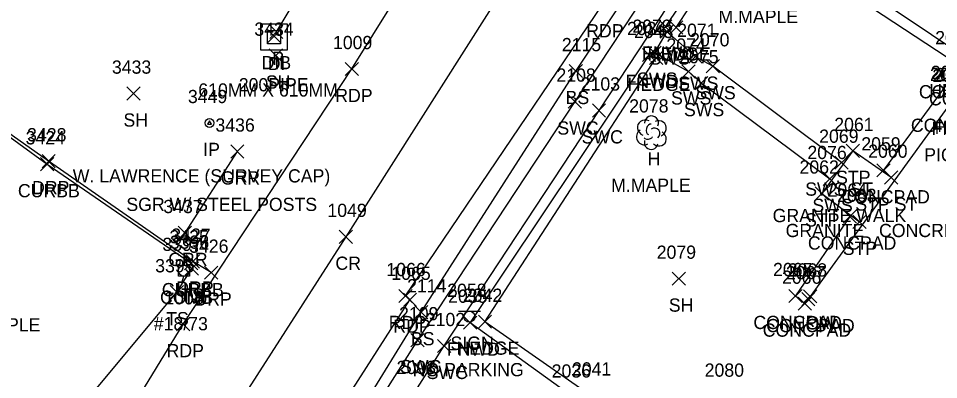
# Model space of a CAD drawing. Extents: x 1634209 to 1639641, y 608564 to 612258.
# Drawn here: x 1639014.2 to 1639153.3, y 611150.8 to 611205.4 of the extents above; entities that cross this region are included whole.
import ezdxf

# ---------------------------------------------------------------- set-up
doc = ezdxf.new("R2010")
doc.units = 0
for name, color, linetype in [('D_A', 7, 'Continuous'), ('D_C', 7, 'Continuous'), ('D_TIC', 7, 'Continuous'), ('DCP', 7, 'Continuous'), ('DS', 7, 'Continuous'), ('L_A', 7, 'Continuous'), ('L_C', 7, 'Continuous'), ('L_I', 7, 'Continuous'), ('L_TIC', 7, 'Continuous'), ('LAHR', 7, 'Continuous'), ('LBC', 7, 'Continuous'), ('LBF', 7, 'Continuous'), ('LELB', 7, 'Continuous'), ('LFNC', 7, 'Continuous'), ('LS', 7, 'Continuous'), ('LTD', 7, 'Continuous'), ('M_A', 7, 'Continuous'), ('M_C', 7, 'Continuous'), ('M_I', 7, 'Continuous'), ('MPIR', 7, 'Continuous'), ('P_A', 7, 'Continuous'), ('P_I', 7, 'Continuous'), ('P_TIC', 7, 'Continuous'), ('PET', 7, 'Continuous'), ('PRC', 7, 'Continuous'), ('R_A', 7, 'Continuous'), ('R_C', 7, 'Continuous'), ('R_I', 7, 'Continuous'), ('R_TIC', 7, 'Continuous'), ('RC', 7, 'Continuous'), ('RDP', 7, 'Continuous'), ('RGR', 7, 'Continuous'), ('RSW', 7, 'Continuous'), ('S_A', 7, 'Continuous'), ('S_C', 7, 'Continuous'), ('S_I', 7, 'Continuous'), ('SSGN', 7, 'Continuous'), ('U_A', 7, 'Continuous'), ('U_C', 7, 'Continuous'), ('U_I', 7, 'Continuous'), ('UP', 7, 'Continuous')]:
    doc.layers.add(name, color=color, linetype=linetype)

msp = doc.modelspace()

# ---------------------------------------------------------------- linework, layer by layer
at = {"layer": 'D_TIC'}
for points in [[(1639051.89, 611201.74), (1639053.89, 611203.74)], [(1639053.89, 611201.74), (1639051.89, 611203.74)], [(1639052.21, 611202.4), (1639054.21, 611204.4)], [(1639054.21, 611202.4), (1639052.21, 611204.4)]]:
    msp.add_lwpolyline(points, dxfattribs=at)
at = {"layer": 'DCP'}
msp.add_lwpolyline([(1639053.21, 611203.4), (1639105.21, 611289.55)], dxfattribs=at)
at = {"layer": 'DS'}
for p, q in [((1639050.85, 611204.61), (1639054.85, 611204.61)), ((1639050.85, 611200.61), (1639050.85, 611204.61)), ((1639054.85, 611204.61), (1639054.85, 611200.61)), ((1639051.85, 611201.61), (1639051.85, 611203.61)), ((1639051.85, 611203.61), (1639053.85, 611203.61)), ((1639053.85, 611203.61), (1639053.85, 611201.61)), ((1639052.86, 611202.61), (1639052.86, 611202.61)), ((1639052.86, 611202.61), (1639052.86, 611202.61)), ((1639054.85, 611200.61), (1639050.85, 611200.61)), ((1639053.85, 611201.61), (1639051.85, 611201.61))]:
    msp.add_line(p, q, dxfattribs=at)
at = {"layer": 'L_TIC'}
for points in [[(1639111.02, 611203.2), (1639113.02, 611205.2)], [(1639113.02, 611203.2), (1639111.02, 611205.2)], [(1639112.65, 611203.04), (1639114.65, 611205.04)], [(1639114.65, 611203.04), (1639112.65, 611205.04)], [(1639052.14, 611198.81), (1639054.14, 611200.81)], [(1639054.14, 611198.81), (1639052.14, 611200.81)], [(1639108.56, 611198.9), (1639110.56, 611200.9)], [(1639110.56, 611198.9), (1639108.56, 611200.9)], [(1639109.62, 611198.46), (1639111.62, 611200.46)], [(1639111.62, 611198.46), (1639109.62, 611200.46)], [(1639097.5, 611196.47), (1639099.5, 611198.47)], [(1639099.5, 611196.47), (1639097.5, 611198.47)], [(1639030.61, 611193.07), (1639032.61, 611195.07)], [(1639032.61, 611193.07), (1639030.61, 611195.07)], [(1639139.37, 611184.4), (1639141.37, 611186.4)], [(1639141.37, 611184.4), (1639139.37, 611186.4)], [(1639143.98, 611181.46), (1639145.98, 611183.46)], [(1639145.98, 611181.46), (1639143.98, 611183.46)], [(1639145.15, 611180.36), (1639147.15, 611182.36)], [(1639147.15, 611180.36), (1639145.15, 611182.36)], [(1639134.68, 611177.96), (1639136.68, 611179.96)], [(1639136.68, 611177.96), (1639134.68, 611179.96)], [(1639138.92, 611174.47), (1639140.92, 611176.47)], [(1639140.92, 611174.47), (1639138.92, 611176.47)], [(1639140.38, 611173.67), (1639142.38, 611175.67)], [(1639142.38, 611173.67), (1639140.38, 611175.67)], [(1639039.42, 611166.6), (1639041.42, 611168.6)], [(1639041.42, 611166.6), (1639039.42, 611168.6)], [(1639113.05, 611165.08), (1639115.05, 611167.08)], [(1639115.05, 611165.08), (1639113.05, 611167.08)], [(1639037.15, 611163.03), (1639039.15, 611165.03)], [(1639039.15, 611163.03), (1639037.15, 611165.03)], [(1639130.68, 611162.46), (1639132.68, 611164.46)], [(1639132.68, 611162.46), (1639130.68, 611164.46)], [(1639132.9, 611162.4), (1639134.9, 611164.4)], [(1639134.9, 611162.4), (1639132.9, 611164.4)], [(1639132.1, 611161.3), (1639134.1, 611163.3)], [(1639134.1, 611161.3), (1639132.1, 611163.3)], [(1639132.63, 611161.98), (1639134.63, 611163.98)], [(1639134.63, 611161.98), (1639132.63, 611163.98)], [(1639074.11, 611160), (1639076.11, 611162)], [(1639076.11, 611160), (1639074.11, 611162)], [(1639081.52, 611158.43), (1639083.52, 611160.43)], [(1639083.52, 611158.43), (1639081.52, 611160.43)], [(1639083.75, 611158.57), (1639085.75, 611160.57)], [(1639085.75, 611158.57), (1639083.75, 611160.57)]]:
    msp.add_lwpolyline(points, dxfattribs=at)
at = {"layer": 'LAHR'}
for points in [[(1639113.65, 611204.04), (1639123.99, 611219.71), (1639156.21, 611198.52)], [(1639101.1, 611140.66), (1639096.39, 611143.28), (1639100.68, 611148.43), (1639084.75, 611159.57), (1639110.62, 611199.46)]]:
    msp.add_lwpolyline(points, dxfattribs=at)
at = {"layer": 'LBC'}
msp.add_lwpolyline([(1639184.89, 611171.79), (1639182.53, 611173.66), (1639182.28, 611173.79), (1639155.36, 611192.97), (1639133.9, 611163.4)], dxfattribs=at)
at = {"layer": 'LBF'}
msp.add_lwpolyline([(1639146.15, 611181.36), (1639140.37, 611185.4), (1639135.68, 611178.96), (1639141.38, 611174.67)], dxfattribs=at)
at = {"layer": 'LELB'}
for points in [[(1639041.81, 611107.81), (1639056.24, 611130.36), (1639075.11, 611161), (1639098.5, 611197.47), (1639122.91, 611234.07), (1639126.22, 611237.88)], [(1638966.07, 611052.28), (1638973.12, 611062.49), (1638979.47, 611078.29), (1638990.68, 611098.4), (1639000.87, 611114.56), (1639014.69, 611135.84), (1639038.15, 611164.03), (1639040.42, 611167.6)]]:
    msp.add_lwpolyline(points, dxfattribs=at)
at = {"layer": 'LFNC'}
for points in [[(1639155.81, 611192.8), (1639159.25, 611198.28), (1639123.95, 611221.97), (1639112.02, 611204.2)], [(1639109.56, 611199.9), (1639082.52, 611159.43), (1639098.22, 611148.12), (1639094.75, 611142.85), (1639099.99, 611139.67)]]:
    msp.add_lwpolyline(points, dxfattribs=at)
at = {"layer": 'LS'}
for points in [[(1639155.49, 611193.27), (1639158.24, 611197.28), (1639156.71, 611198.34), (1639144.98, 611182.46)], [(1639139.92, 611175.47), (1639131.68, 611163.46), (1639133.1, 611162.3), (1639133.63, 611162.98)]]:
    msp.add_lwpolyline(points, dxfattribs=at)
at = {"layer": 'LTD'}
msp.add_line((1639109.88, 611188.2), (1639109.88, 611188.2), dxfattribs=at)
msp.add_line((1639109.88, 611188.2), (1639109.88, 611188.2), dxfattribs=at)
msp.add_arc((1639109.93, 611189.63), 1.05, 335.5272, 180.9563, dxfattribs=at)
for centre, major_axis, ratio, start_param, end_param in [((1639109.09, 611188.86), (1.21, -0.51), 0.895232, 1.570796, 4.712389), ((1639109.68, 611188.65), (-0.208, -0.792), 0.645439, 3.141593, 6.283185), ((1639110.93, 611188.78), (-1.14, -0.48), 0.949671, 1.570796, 4.712389), ((1639108.8, 611187.49), (0.58, -1.04), 0.959034, 3.141593, 6.283185), ((1639110.38, 611188.03), (-0.5, 0.667), 0.989748, 3.141593, 6.283185), ((1639110.88, 611187.36), (-1.09, 0.79), 0.841452, 1.570796, 4.712389), ((1639109.88, 611186.7), (0.26, 1.06), 0.942809, 1.570796, 4.712389), ((1639109.43, 611187.45), (-0.625, -0.083), 0.423636, 0, 3.141593)]:
    msp.add_ellipse(centre, major_axis=major_axis, ratio=ratio, start_param=start_param, end_param=end_param, dxfattribs=at)
at = {"layer": 'MPIR'}
msp.add_lwpolyline([(1639043.11, 611189.95), (1639042.82, 611189.45), (1639043.4, 611189.45)], close=True, dxfattribs=at)
msp.add_circle((1639043.11, 611189.62), 0.667, dxfattribs=at)
at = {"layer": 'P_TIC'}
for points in [[(1639063.62, 611196.78), (1639065.62, 611198.78)], [(1639065.62, 611196.78), (1639063.62, 611198.78)], [(1639062.71, 611171.41), (1639064.71, 611173.41)], [(1639064.71, 611171.41), (1639062.71, 611173.41)], [(1639071.72, 611162.46), (1639073.72, 611164.46)], [(1639073.72, 611162.46), (1639071.72, 611164.46)], [(1639072.41, 611161.89), (1639074.41, 611163.89)], [(1639074.41, 611161.89), (1639072.41, 611163.89)], [(1639038.12, 611158.19), (1639040.12, 611160.19)], [(1639040.12, 611158.19), (1639038.12, 611160.19)]]:
    msp.add_lwpolyline(points, dxfattribs=at)
at = {"layer": 'PET'}
for points in [[(1638854.83, 610853.22), (1638885.37, 610909), (1638902.82, 610937.28), (1638929.33, 610982.56), (1638950.92, 611019.42), (1638971.29, 611051.92), (1639000.04, 611096.96), (1639023.57, 611133.7), (1639039.12, 611159.19), (1639064.62, 611197.78), (1639080.51, 611223.3), (1639114.23, 611277.34), (1639131.17, 611302.28), (1639149.64, 611331.79), (1639176.42, 611372.35), (1639193.48, 611398.88), (1639220.96, 611441.47), (1639247.22, 611483.75)], [(1638878.4, 610839.82), (1638902.26, 610883.1), (1638925.76, 610925.06), (1638957.25, 610978.12), (1638978.73, 611014.12), (1639004.29, 611055.32), (1639040.97, 611112.28), (1639073.41, 611162.89), (1639072.72, 611163.46), (1639102.57, 611207.56), (1639124.27, 611240.99), (1639140.69, 611264.29), (1639156.2, 611287.4), (1639175.63, 611318.1), (1639189.77, 611341.61), (1639219.88, 611389.38), (1639245.26, 611428.04), (1639265.27, 611462.65)]]:
    msp.add_lwpolyline(points, dxfattribs=at)
at = {"layer": 'PRC'}
msp.add_lwpolyline([(1639250.46, 611462.84), (1639222.36, 611418.18), (1639195.34, 611376.28), (1639169.71, 611336.75), (1639147.17, 611302.78), (1639120.59, 611261.16), (1639092.55, 611217.83), (1639063.71, 611172.41), (1639032.46, 611123.7), (1639004.79, 611080.3), (1638977.88, 611037.27), (1638950.44, 610992.13), (1638925.96, 610950.29), (1638900.29, 610905.36), (1638879.75, 610869.2), (1638867.15, 610846.08)], dxfattribs=at)
at = {"layer": 'R_TIC'}
for points in [[(1639111.25, 611202.45), (1639113.25, 611204.45)], [(1639113.25, 611202.45), (1639111.25, 611204.45)], [(1639109.37, 611199.25), (1639111.37, 611201.25)], [(1639111.37, 611199.25), (1639109.37, 611201.25)], [(1639115.59, 611198.64), (1639117.59, 611200.64)], [(1639117.59, 611198.64), (1639115.59, 611200.64)], [(1639118.19, 611197.2), (1639120.19, 611199.2)], [(1639120.19, 611197.2), (1639118.19, 611199.2)], [(1639114.51, 611196.41), (1639116.51, 611198.41)], [(1639116.51, 611196.41), (1639114.51, 611198.41)], [(1639116.46, 611194.64), (1639118.46, 611196.64)], [(1639118.46, 611194.64), (1639116.46, 611196.64)], [(1639097.32, 611191.86), (1639099.32, 611193.86)], [(1639099.32, 611191.86), (1639097.32, 611193.86)], [(1639100.99, 611190.52), (1639102.99, 611192.52)], [(1639102.99, 611190.52), (1639100.99, 611192.52)], [(1639046.31, 611184.31), (1639048.31, 611186.31)], [(1639048.31, 611184.31), (1639046.31, 611186.31)], [(1639017.56, 611182.38), (1639019.56, 611184.38)], [(1639019.56, 611182.38), (1639017.56, 611184.38)], [(1639017.79, 611182.84), (1639019.79, 611184.84)], [(1639019.79, 611182.84), (1639017.79, 611184.84)], [(1639137.66, 611182.62), (1639139.66, 611184.62)], [(1639139.66, 611182.62), (1639137.66, 611184.62)], [(1639135.88, 611180.16), (1639137.88, 611182.16)], [(1639137.88, 611180.16), (1639135.88, 611182.16)], [(1639038.39, 611171.99), (1639040.39, 611173.99)], [(1639040.39, 611171.99), (1639038.39, 611173.99)], [(1639039.32, 611167.42), (1639041.32, 611169.42)], [(1639041.32, 611167.42), (1639039.32, 611169.42)], [(1639039.59, 611167.66), (1639041.59, 611169.66)], [(1639041.59, 611167.66), (1639039.59, 611169.66)], [(1639042.34, 611165.99), (1639044.34, 611167.99)], [(1639044.34, 611165.99), (1639042.34, 611167.99)], [(1639073.54, 611155.78), (1639075.54, 611157.78)], [(1639075.54, 611155.78), (1639073.54, 611157.78)], [(1639077.57, 611154.9), (1639079.57, 611156.9)], [(1639079.57, 611154.9), (1639077.57, 611156.9)]]:
    msp.add_lwpolyline(points, dxfattribs=at)
at = {"layer": 'RC'}
msp.add_lwpolyline([(1639005.65, 611192.75), (1639018.56, 611183.38), (1639040.32, 611168.42)], dxfattribs=at)
at = {"layer": 'RDP'}
msp.add_lwpolyline([(1639043.34, 611166.99), (1639040.59, 611168.66), (1639018.79, 611183.84), (1639005.52, 611193.16)], dxfattribs=at)
at = {"layer": 'RGR'}
msp.add_lwpolyline([(1639047.31, 611185.31), (1639039.39, 611172.99)], dxfattribs=at)
at = {"layer": 'RSW'}
for points in [[(1639046.01, 611105.02), (1639061.85, 611129.55), (1639078.57, 611155.9), (1639101.99, 611191.52), (1639128.62, 611231.94), (1639130.78, 611235.12), (1639127.67, 611237.28), (1639125.39, 611233.9), (1639098.32, 611192.86), (1639074.54, 611156.78), (1639058.01, 611130.67), (1639042.92, 611107.1)], [(1639138.66, 611183.62), (1639119.19, 611198.2), (1639116.59, 611199.64), (1639112.25, 611203.45), (1639110.37, 611200.25), (1639115.51, 611197.41), (1639117.46, 611195.64), (1639136.88, 611181.16)]]:
    msp.add_lwpolyline(points, dxfattribs=at)
at = {"layer": 'SSGN'}
for p, q in [((1639080.76, 611161.17), (1639084.09, 611161.17)), ((1639082.4, 611160.34), (1639082.4, 611160.34))]:
    msp.add_line(p, q, dxfattribs=at)
msp.add_circle((1639082.4, 611160.34), 0.833, dxfattribs=at)
at = {"layer": 'UP'}
for p, q in [((1639039.49, 611168.94), (1639039.24, 611168.1)), ((1639038.41, 611166.44), (1639038.41, 611168.1)), ((1639038.41, 611168.1), (1639040.08, 611168.1)), ((1639039.24, 611167.27), (1639039.24, 611167.27)), ((1639040.08, 611168.1), (1639040.08, 611166.44)), ((1639040.08, 611166.44), (1639038.41, 611166.44)), ((1639038.99, 611165.6), (1639039.24, 611166.44))]:
    msp.add_line(p, q, dxfattribs=at)
msp.add_circle((1639039.24, 611167.27), 0.833, dxfattribs=at)

# ---------------------------------------------------------------- texts
at = {"layer": 'D_A'}
for s, p in [('P', (1639052.59, 611198.4)), ('DIB', (1639050.99, 611197.74)), ('DI', (1639051.91, 611197.61))]:
    msp.add_text(s, height=2, dxfattribs=at).set_placement(p)
at = {"layer": 'D_C'}
for s, p in [('200PIPE', (1639047.53, 611194.4)), ('610MM X 610MM', (1639041.41, 611193.61))]:
    msp.add_text(s, height=2, dxfattribs=at).set_placement(p)
at = {"layer": 'L_A'}
for s, p in [('FNWD', (1639108.48, 611199.2)), ('HEDGE', (1639109.35, 611199.04)), ('SH', (1639051.63, 611194.81)), ('FNWD', (1639106.02, 611194.9)), ('HEDGE', (1639106.32, 611194.46)), ('CONCPAD', (1639150.35, 611193.34)), ('HEDGE', (1639151.91, 611193.52)), ('BS', (1639096.94, 611192.47)), ('CONCPAD', (1639151.89, 611192.28)), ('SH', (1639030.1, 611189.07)), ('CONCPAD', (1639149.14, 611188.27)), ('FNWD', (1639152.28, 611187.8)), ('HOW', (1639152.74, 611187.97)), ('H', (1639109.32, 611183.2)), ('STP', (1639137.83, 611180.4)), ('CONCPAD', (1639138.63, 611177.46)), ('STP ST', (1639140.74, 611176.36)), ('STP', (1639133.14, 611173.96)), ('CONCPAD', (1639133.57, 611170.47)), ('STP', (1639138.84, 611169.67)), ('TS', (1639038.83, 611162.6)), ('SH', (1639112.54, 611161.08)), ('TS', (1639036.55, 611159.03)), ('CONCPAD', (1639125.33, 611158.46)), ('CONCPAD', (1639127.27, 611157.98)), ('HOW', (1639131.29, 611158.4)), ('CONCPAD', (1639126.74, 611157.3)), ('BS', (1639073.55, 611156)), ('FNWD', (1639078.98, 611154.43)), ('HEDGE', (1639080.45, 611154.57))]:
    msp.add_text(s, height=2, dxfattribs=at).set_placement(p)
at = {"layer": 'L_C'}
for s, p in [('M.MAPLE', (1639120.06, 611204.72)), ('PICKET', (1639151.15, 611183.8)), ('M.MAPLE', (1639103.82, 611179.2)), ('GRANITE   CONCRETE', (1639130.2, 611172.36)), ('M.MAPLE', (1639005.51, 611158.1))]:
    msp.add_text(s, height=2, dxfattribs=at).set_placement(p)
at = {"layer": 'L_I'}
for s, p in [('3434', (1639049.88, 611202.81)), ('2034', (1639106.22, 611202.9)), ('2043', (1639107.28, 611202.46)), ('2046', (1639152.81, 611201.52)), ('2115', (1639096.37, 611200.47)), ('3433', (1639028.35, 611197.07)), ('2054', (1639152.02, 611195.97)), ('2055', (1639152.15, 611196.27)), ('2030', (1639152.39, 611195.8)), ('2078', (1639106.55, 611191.2)), ('2061', (1639137.55, 611188.4)), ('2059', (1639141.64, 611185.46)), ('2060', (1639142.68, 611184.36)), ('2062', (1639132.3, 611181.96)), ('2064', (1639136.54, 611178.47)), ('2063', (1639137.99, 611177.67)), ('3396', (1639037.11, 611170.6)), ('2079', (1639110.71, 611169.08)), ('3395', (1639034.89, 611167.03)), ('2065', (1639128.3, 611166.46)), ('2068', (1639130.52, 611166.4)), ('2066', (1639129.66, 611165.3)), ('2067', (1639130.24, 611165.98)), ('2114', (1639072.98, 611164)), ('2035', (1639079.18, 611162.43)), ('2042', (1639081.41, 611162.57)), ('2036', (1639094.83, 611151.12)), ('2041', (1639097.9, 611151.43)), ('2080', (1639117.96, 611151.25))]:
    msp.add_text(s, height=2, dxfattribs=at).set_placement(p)
at = {"layer": 'M_A'}
msp.add_text('IP', height=2, dxfattribs=at).set_placement((1639042.15, 611184.62))
at = {"layer": 'M_C'}
msp.add_text('W. LAWRENCE (SURVEY CAP)', height=2, dxfattribs=at).set_placement((1639022.43, 611180.62))
at = {"layer": 'M_I'}
msp.add_text('3449', height=2, dxfattribs=at).set_placement((1639039.84, 611192.62))
at = {"layer": 'P_A'}
for s, p in [('RDP', (1639100.05, 611202.56)), ('RDP', (1639062.11, 611192.78)), ('CR', (1639062.14, 611167.41)), ('RDP', (1639070.2, 611158.46)), ('RDP', (1639070.89, 611157.89)), ('RDP', (1639036.61, 611154.19))]:
    msp.add_text(s, height=2, dxfattribs=at).set_placement(p)
at = {"layer": 'P_I'}
for s, p in [('1009', (1639061.77, 611200.78)), ('1049', (1639060.93, 611175.41)), ('1066', (1639069.84, 611166.46)), ('1065', (1639070.59, 611165.89)), ('1008', (1639036.27, 611162.19))]:
    msp.add_text(s, height=2, dxfattribs=at).set_placement(p)
at = {"layer": 'R_A'}
for s, p in [('SWS', (1639109.62, 611198.45)), ('SWS', (1639107.74, 611195.25)), ('SWS', (1639113.96, 611194.64)), ('SWS', (1639116.56, 611193.2)), ('SWS', (1639112.88, 611192.41)), ('SWS', (1639114.83, 611190.64)), ('SWC', (1639095.69, 611187.86)), ('SWC', (1639099.36, 611186.52)), ('GRR', (1639044.8, 611180.31)), ('CURBB', (1639014.14, 611178.38)), ('DRP', (1639016.28, 611178.84)), ('SWS ST', (1639133.16, 611178.62)), ('SWS', (1639134.25, 611176.16)), ('GRR', (1639036.87, 611167.99)), ('DRP', (1639038.08, 611163.66)), ('CURBB', (1639035.9, 611163.42)), ('DRP', (1639040.82, 611161.99)), ('SWC', (1639071.9, 611151.78)), ('SWC', (1639075.93, 611150.9))]:
    msp.add_text(s, height=2, dxfattribs=at).set_placement(p)
at = {"layer": 'R_C'}
for s, p in [('SGR W/ STEEL POSTS', (1639030.54, 611176.31)), ('GRANITE WALK', (1639128.24, 611174.62))]:
    msp.add_text(s, height=2, dxfattribs=at).set_placement(p)
at = {"layer": 'R_I'}
for s, p in [('2073', (1639107.03, 611203.25)), ('2071', (1639113.81, 611202.64)), ('2070', (1639115.76, 611201.2)), ('2074', (1639112.18, 611200.41)), ('2075', (1639114.12, 611198.64)), ('2108', (1639095.55, 611195.86)), ('2029', (1639152.82, 611195.93)), ('2103', (1639099.22, 611194.52)), ('3436', (1639044, 611188.31)), ('3424', (1639015.3, 611186.38)), ('3428', (1639015.53, 611186.84)), ('2069', (1639135.27, 611186.62)), ('2076', (1639133.49, 611184.16)), ('3437', (1639036.13, 611175.99)), ('3425', (1639037.06, 611171.42)), ('3427', (1639037.33, 611171.66)), ('3426', (1639040.02, 611169.99)), ('2109', (1639071.76, 611159.78)), ('2102', (1639075.8, 611158.9)), ('2093', (1639071.39, 611151.65))]:
    msp.add_text(s, height=2, dxfattribs=at).set_placement(p)
at = {"layer": 'S_A'}
msp.add_text('SIGN', height=2, dxfattribs=at).set_placement((1639079.54, 611155.32))
at = {"layer": 'S_C'}
msp.add_text('NO PARKING', height=2, dxfattribs=at).set_placement((1639073.82, 611151.32))
at = {"layer": 'S_I'}
msp.add_text('2058', height=2, dxfattribs=at).set_placement((1639079.04, 611163.32))
at = {"layer": 'U_A'}
msp.add_text('COMB', height=2, dxfattribs=at).set_placement((1639035.63, 611162.27))
at = {"layer": 'U_C'}
msp.add_text('#18/73', height=2, dxfattribs=at).set_placement((1639034.68, 611158.27))
at = {"layer": 'U_I'}
msp.add_text('3397', height=2, dxfattribs=at).set_placement((1639035.98, 611170.27))

doc.saveas('drawing.dxf')
